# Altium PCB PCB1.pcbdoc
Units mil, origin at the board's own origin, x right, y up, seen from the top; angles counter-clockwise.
Board outline 3937.01 x 3937.01 mil, 2 copper layers (Top Layer, Bottom Layer); 25 components, 44 nets, 119 pads, 18 vias.
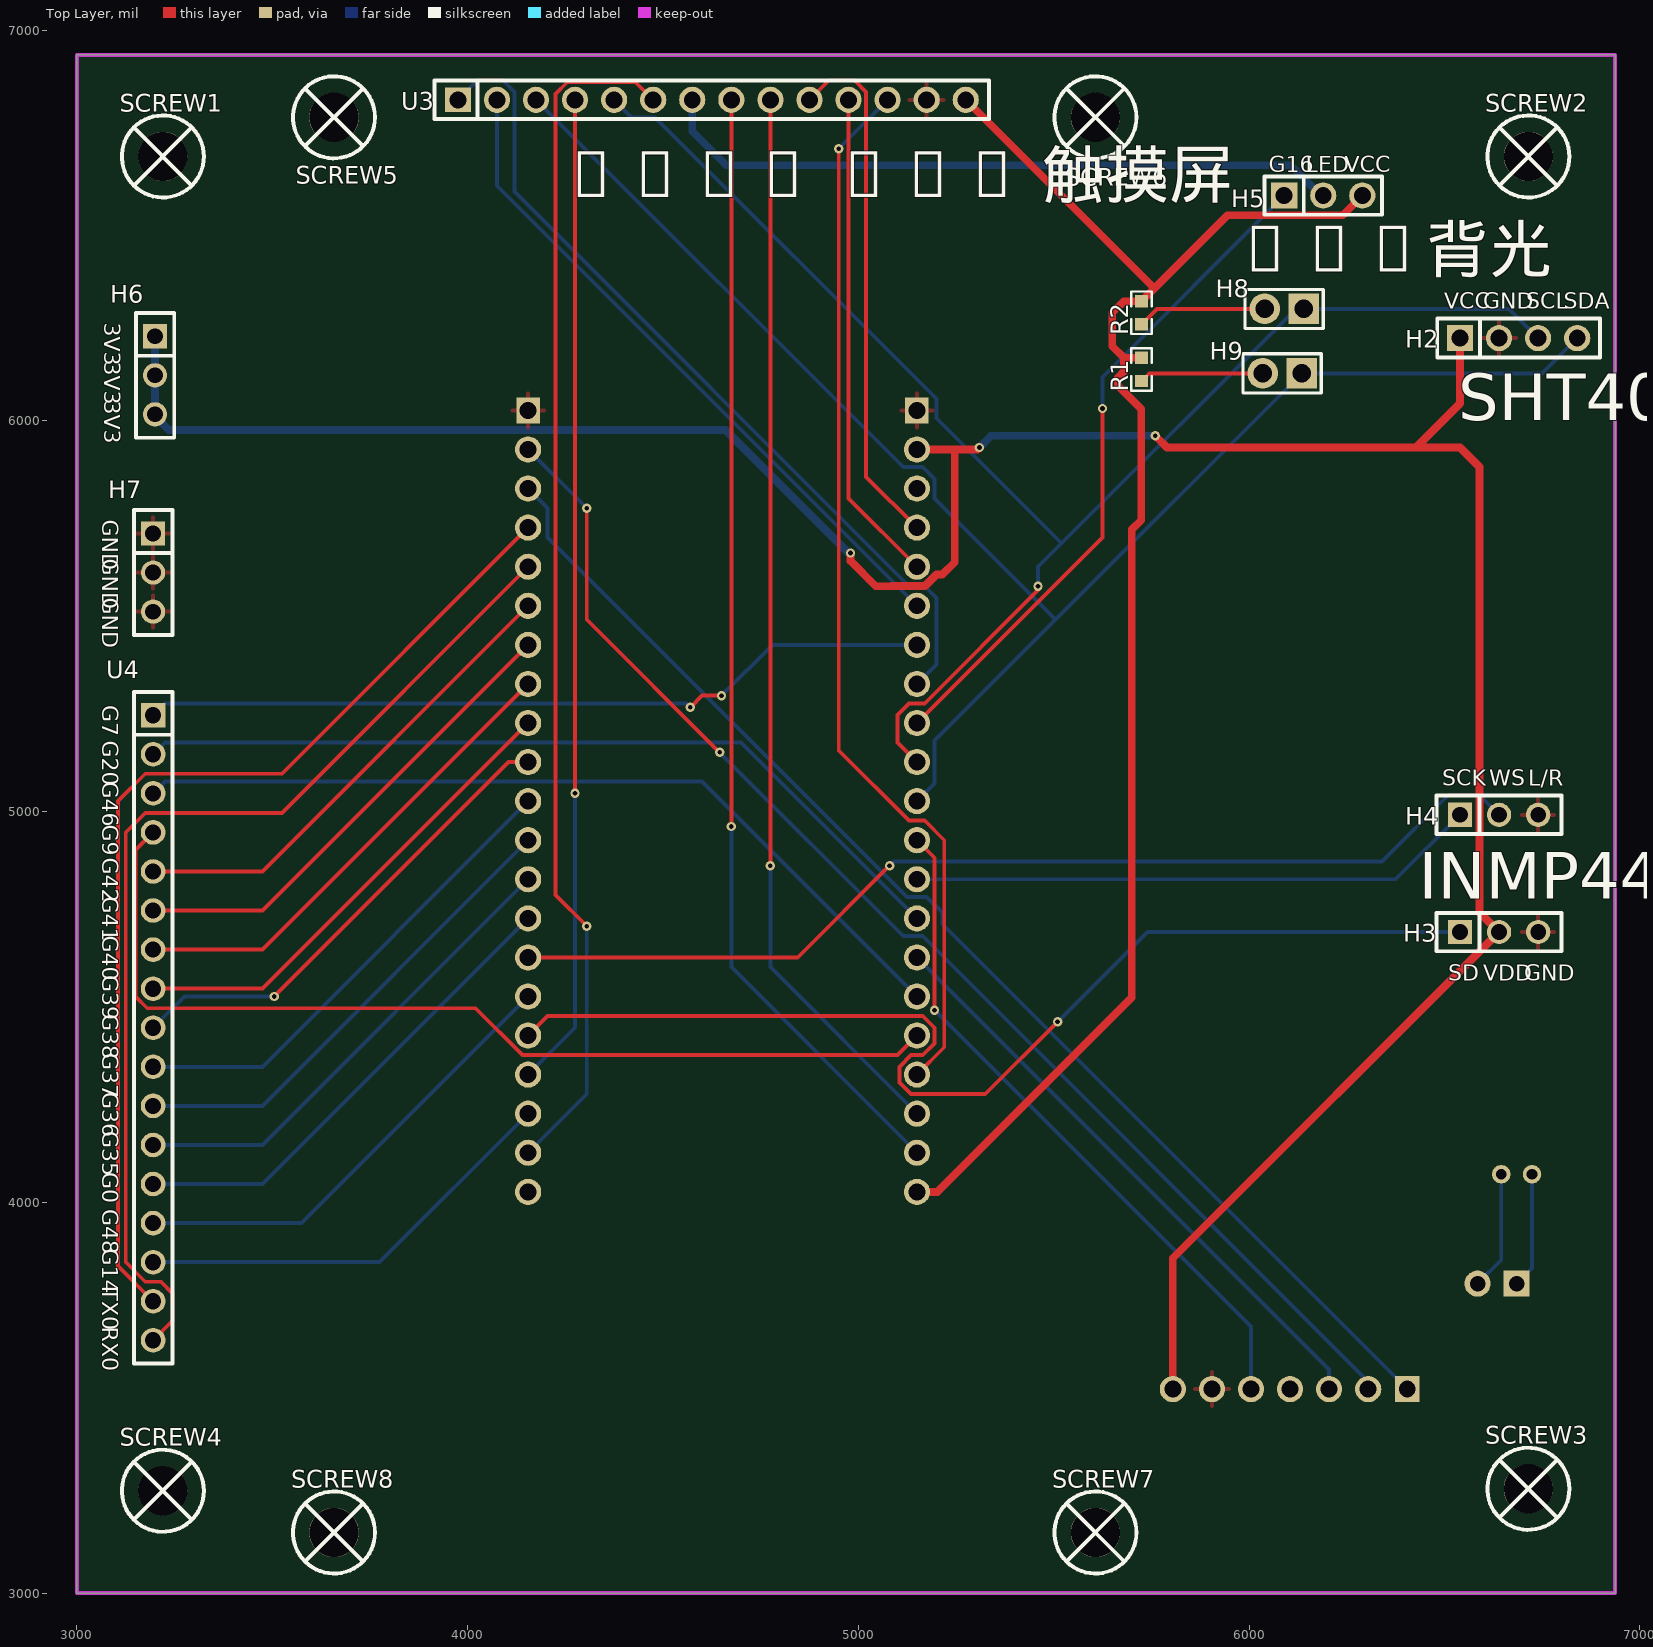
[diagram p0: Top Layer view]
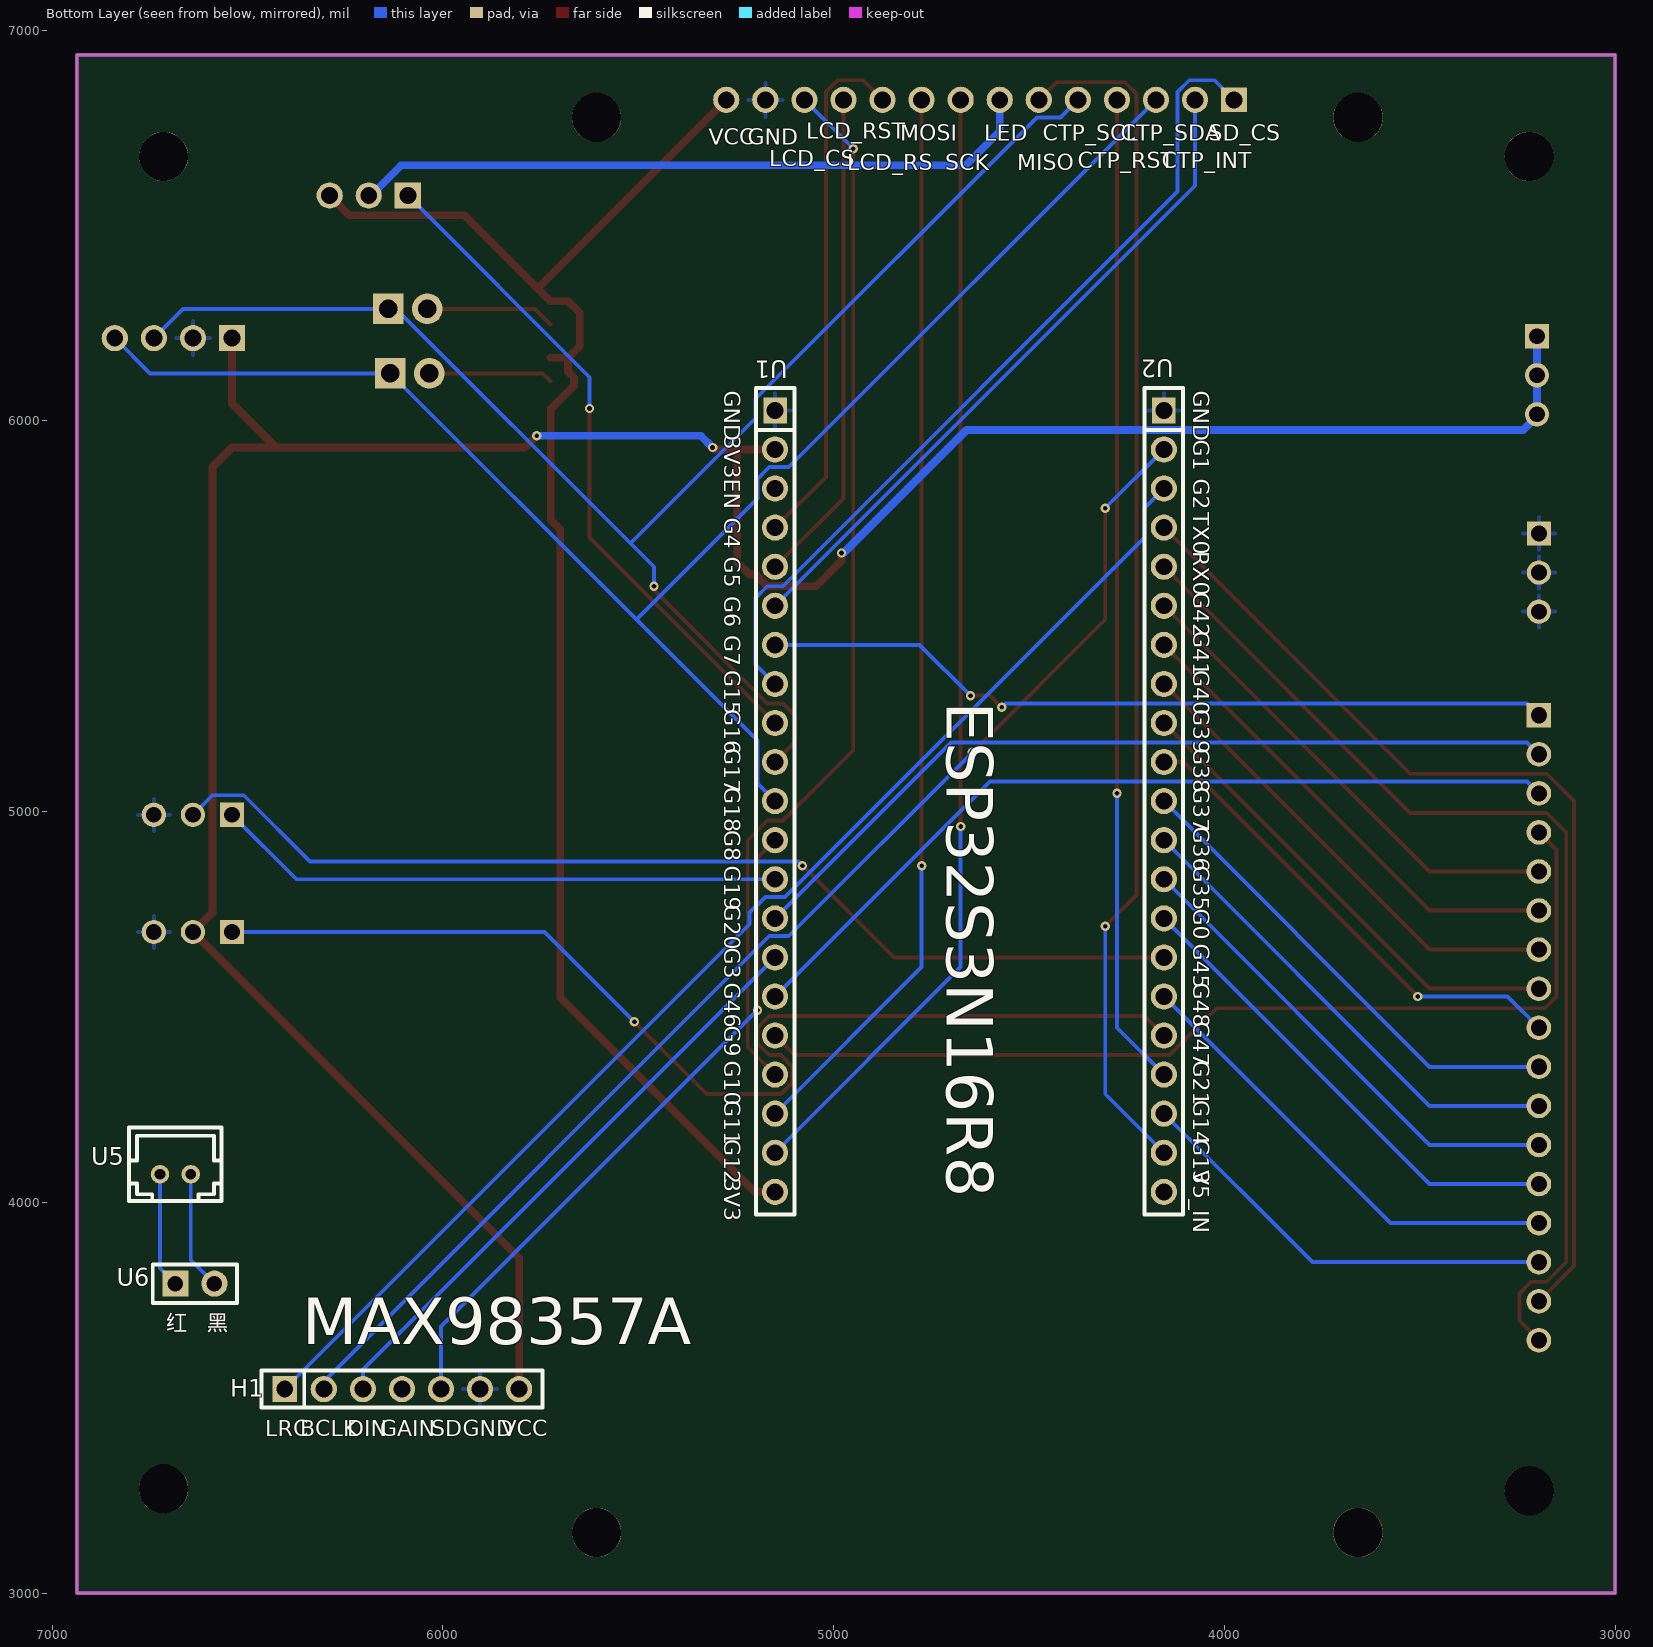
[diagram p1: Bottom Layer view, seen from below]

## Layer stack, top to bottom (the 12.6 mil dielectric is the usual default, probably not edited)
Top Layer: signal copper (thickness not stored)
Dielectric: dielectric 12.6, FR-4, Dk 4.8
Bottom Layer: signal copper (thickness not stored)

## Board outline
3000,6937.01 6937.01,6937.01 6937.01,3000 3000,3000

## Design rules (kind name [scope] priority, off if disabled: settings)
BoardOutlineClearance copperThickness1oz [All] p0: genericclearance=10 ignorepadtopadclearanceinfootprint=FALSE except(0: Arc-SplitContinuation Track-SplitContinuation SMDPad-SplitContinuation THPad-SplitContinuation Via-SplitContinuation Fill-SplitContinuation Poly-SplitContinuation Region-SplitContinuation Text-SplitContinuation; 6: Track-CutoutEdge SMDPad-CutoutEdge THPad-CutoutEdge Via-CutoutEdge Region-CutoutEdge; 11.8: Track-OutlineEdge SMDPad-OutlineEdge THPad-OutlineEdge Via-OutlineEdge Fill-OutlineEdge Region-OutlineEdge Poly-OutlineEdge Text-OutlineEdge Fill-CutoutEdge)
BoardOutlineClearance copperThickness2oz [All] p0: genericclearance=10 ignorepadtopadclearanceinfootprint=FALSE except(0: Arc-SplitContinuation Track-SplitContinuation SMDPad-SplitContinuation THPad-SplitContinuation Via-SplitContinuation Fill-SplitContinuation Poly-SplitContinuation Region-SplitContinuation Text-SplitContinuation; 6: Track-CutoutEdge SMDPad-CutoutEdge THPad-CutoutEdge Via-CutoutEdge Region-CutoutEdge; 11.8: Track-OutlineEdge SMDPad-OutlineEdge THPad-OutlineEdge Via-OutlineEdge Fill-OutlineEdge Region-OutlineEdge Poly-OutlineEdge Text-OutlineEdge Fill-CutoutEdge)
Clearance copperThickness1oz [(InNet('GND') OR InNet('DIN') OR InNet('BCLK') OR InNet('LRC') OR InNet('WS') OR InNet('SCK') OR InNet('VCC3.3V') OR InNet('GPIO7') OR InNet('GPIO16') OR InNet('GPIO20') OR InNet('GPIO46') OR InNet('GPIO9') OR InNet('TXD0') OR InNet('RXD0') OR InNet('GPIO42') OR InNet('GPIO41') OR InNet('GPIO40') OR InNet('GPIO39') OR InNet('GPIO38') OR InNet('GPIO37') OR InNet('GPIO36') OR InNet('GPIO35') OR InNet('GPIO0') OR InNet('GPIO48') OR InNet('GPIO14') OR InNet('LCD_CS') OR InNet('LCD_RST') OR InNet('LCD_RS') OR InNet('MOSI') OR InNet('LED') OR InNet('MISO') OR InNet('CTP_SCL') OR InNet('CTP_RST') OR InNet('CTP_SDA') OR InNet('CTP_INT') OR InNet('SD_CS') OR InNet('MAX_SD') OR InNet('IP_SD') OR InNet('IP_SCK') OR InNet('3V3') OR InNet('CTP_SCL1') OR InNet('CTP_SDA1') OR InNet('-') OR InNet('+'))] p1: gap=7 ignorepadtopadclearanceinfootprint=FALSE except(4: Track-Track; 6: Track-SMDPad SMDPad-SMDPad Track-THPad SMDPad-THPad THPad-THPad Track-Via SMDPad-Via THPad-Via Via-Via SMDPad-Fill THPad-Fill Via-Fill Fill-Fill Track-Region SMDPad-Region THPad-Region Via-Region Region-Region Track-Poly SMDPad-Poly THPad-Poly Via-Poly Fill-Poly Region-Poly Poly-Poly Track-Text SMDPad-Text THPad-Text Via-Text Fill-Text Region-Text Poly-Text Text-Text; 6.9: Track-Hole SMDPad-Hole THPad-Hole Via-Hole Fill-Hole Region-Hole Poly-Hole Text-Hole Sheet-Hole; 11.8: Track-Fill Fill-Region Track-Sheet SMDPad-Sheet THPad-Sheet Via-Sheet Fill-Sheet Region-Sheet Poly-Sheet Text-Sheet)
Clearance copperThickness2oz [All] p1: gap=7 ignorepadtopadclearanceinfootprint=FALSE except(6: Track-SMDPad SMDPad-SMDPad Track-THPad SMDPad-THPad THPad-THPad Track-Via SMDPad-Via THPad-Via Via-Via SMDPad-Fill THPad-Fill Via-Fill Fill-Fill Track-Region SMDPad-Region THPad-Region Via-Region Region-Region Track-Poly SMDPad-Poly THPad-Poly Via-Poly Fill-Poly Region-Poly Poly-Poly Track-Text SMDPad-Text THPad-Text Via-Text Fill-Text Region-Text Poly-Text Text-Text; 6.9: Track-Hole SMDPad-Hole THPad-Hole Via-Hole Fill-Hole Region-Hole Poly-Hole Text-Hole Sheet-Hole; 8: Track-Track; 11.8: Track-Fill Fill-Region Track-Sheet SMDPad-Sheet THPad-Sheet Via-Sheet Fill-Sheet Region-Sheet Poly-Sheet Text-Sheet)
DiffPairsRouting differentialPair [All] p1: maxuncoupledlength=10 minlimit=6 maxlimit=6 mostfreqgap=6 toplayer_minwidth=5 toplayer_prefwidth=10 toplayer_maxwidth=100 bottomlayer_minwidth=5 bottomlayer_prefwidth=10 bottomlayer_maxwidth=100
PasteMaskExpansion pasteMaskExpansion [All] p1: expansion=0
PlaneConnect innerPlane [All] p1: planeconnectstyle=Relief reliefexpansion=20 reliefentries=4 reliefconductorwidth=10 reliefairgap=10
PolygonConnect copperRegion [All] p1: connectstyle=Relief reliefentries=4 reliefconductorwidth=10 polygonreliefangle="90 Angle" airgapwidth=10
RoutingVias viaSize [All] p1: viastyle="Through Hole" holewidth=12.0078 minholewidth=11.811 maxholewidth=248.0314 width=24.0158 minwidth=19.685 maxwidth=393.7008
SolderMaskExpansion solderMaskExpansion [All] p1: useseparateexpansions=TRUE expansion=2 expansionbottom=2
Width copperThickness1oz [All] p1: maxlimit=100 minlimit=5 preferedwidth=10
Width copperThickness2oz [All] p1: maxlimit=100 minlimit=8 preferedwidth=10

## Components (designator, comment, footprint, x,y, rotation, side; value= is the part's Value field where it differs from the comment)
H1 "PM254V-11-07-H85" HDR-TH_7P-P2.54-V-F 6105,3522.01 r180 bottom
H2 "2.54-1*4P母" HDR-TH_4P-P2.54-V-F 6690,6212.01 r0 top
H3 "X6511FV-03-C85D32" HDR-TH_3P-P2.54-V-F 6640,4692.01 r0 top
H4 "X6511FV-03-C85D32" HDR-TH_3P-P2.54-V-F 6640,4992.01 r0 top
H5 "PZ254V-11-03P" HDR-TH_3P-P2.54-V-M 6190,6577.01 r0 top
H6 "X6511FV-03-C85D32" HDR-TH_3P-P2.54-V-F 3200,6117.01 r270 top
H7 "X6511FV-03-C85D32" HDR-TH_3P-P2.54-V-F 3195,5612.01 r270 top
H8 "PZ254V-11-02P" HDR-TH_2P-P2.54-V-M 6090,6287.01 r180 top
H9 "PZ254V-11-02P" HDR-TH_2P-P2.54-V-M 6085,6122.01 r180 top
R1 "RCA034K7JLF" R0603 5725,6132.01 r90 top
R2 "RCA034K7JLF" R0603 5725,6277.01 r90 top
SCREW1 "M3螺丝" M3螺丝 3220,6677.01 r0 top
SCREW2 "M3螺丝" M3螺丝 6715,6677.01 r0 top
SCREW3 "M3螺丝" M3螺丝 6715,3267.01 r0 top
SCREW4 "M3螺丝" M3螺丝 3220,3262.01 r0 top
SCREW5 "M3螺丝" M3螺丝 3658.07,6777.17 r0 top
SCREW6 "M3螺丝" M3螺丝 5606.89,6777.17 r0 top
SCREW7 "M3螺丝" M3螺丝 5606.89,3155.12 r0 top
SCREW8 "M3螺丝" M3螺丝 3658.07,3155.12 r0 top
U1 "HC-PM254-8.5H-1x21PZ" HDR-TH_21P-P2.54-V-F_1 5150,5027.01 r270 bottom
U2 "HC-PM254-8.5H-1x21PZ" HDR-TH_21P-P2.54-V-F_1 4155,5027.01 r270 bottom
U3 "PM254-1-14-Z-8.5" HDR-TH_14P-P2.54-V-F-1 4625,6822.01 r0 top
U4 "PM254-1-17-Z-8.5" HDR-TH_17P-P2.54-V-F 3195,4447.01 r270 top
U5 "HX 2.0mm-2P ZZ-MS" CONN-TH_2P-P2.00_HX-2.0MM-2P-ZZ 6685,4072.01 r180 bottom
U6 "ZX-PM2.54-1-2PY" HDR-TH_2P-P2.54-V-F 6635,3792.01 r180 bottom

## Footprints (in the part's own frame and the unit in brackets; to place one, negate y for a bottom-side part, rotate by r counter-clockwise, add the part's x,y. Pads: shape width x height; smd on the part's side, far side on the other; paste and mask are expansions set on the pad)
CONN-TH_2P-P2.00_HX-2.0MM-2P-ZZ [mm]
  round 1.2 hole 0.7: 1(-1,0) 2(1,0)
  silkscreen extent -3,-1.75 3,3.05
HDR-TH_2P-P2.54-V-F [mm]
  rect 1.7x1.7 hole 1: 1(-1.27,0)
  round 1.7 hole 1: 2(1.27,0)
  silkscreen extent -2.74,-1.25 2.74,1.25
HDR-TH_2P-P2.54-V-M [mm]
  rect 2x2 hole 1.2: 1(-1.27,0)
  round 2 hole 1.2: 2(1.27,0)
  silkscreen extent -2.54,-1.27 2.54,1.27
HDR-TH_3P-P2.54-V-F [mil]
  rect 62x62 hole 40.16: 1(-100,0)
  round 62 hole 40.16: 2(0,0) 3(100,0)
  silkscreen extent -160,-49 160,49
HDR-TH_3P-P2.54-V-M [mm]
  rect 1.7x1.7 hole 1.1: 1(-2.54,0)
  round 1.7 hole 1.1: 2(0,0) 3(2.54,0)
  silkscreen extent -3.81,-1.25 3.81,1.25
HDR-TH_4P-P2.54-V-F [mm]
  rect 1.7x1.7 hole 1.1: 1(-3.81,0)
  round 1.7 hole 1.1: 2(-1.27,0) 3(1.27,0) 4(3.81,0)
  silkscreen extent -5.29,-1.27 5.29,1.27
HDR-TH_7P-P2.54-V-F [mm]
  rect 1.575x1.7 hole 1.1: 1(-7.62,0)
  round 1.7 hole 1.1: 2(-5.08,0) 3(-2.54,0) 4(0,0) 5(2.54,0) 6(5.08,0) 7(7.62,0)
  silkscreen extent -9.13,-1.2 9.13,1.2
HDR-TH_14P-P2.54-V-F-1 [mm]
  rect 1.7x1.575 hole 1.1: 1(-16.51,0)
  round 1.7 hole 1.1: 2(-13.97,0) 3(-11.43,0) 4(-8.89,0) 5(-6.35,0) 6(-3.81,0) 7(-1.27,0) 8(1.27,0) 9(3.81,0) 10(6.35,0) 11(8.89,0) 12(11.43,0) 13(13.97,0) 14(16.51,0)
  silkscreen extent -18.03,-1.25 18.03,1.25
HDR-TH_17P-P2.54-V-F [mm]
  rect 1.6x1.6 hole 1.05: 1(-20.32,0)
  round 1.6 hole 1.05: 2(-17.78,0) 3(-15.24,0) 4(-12.7,0) 5(-10.16,0) 6(-7.62,0) 7(-5.08,0) 8(-2.54,0) 9(0,0) 10(2.54,0) 11(5.08,0) 12(7.62,0) 13(10.16,0) 14(12.7,0) 15(15.24,0) 16(17.78,0) 17(20.32,0)
  silkscreen extent -21.84,-1.25 21.84,1.25
HDR-TH_21P-P2.54-V-F_1 [mm]
  rect 1.7x1.524 hole 1.1: 1(-25.4,0)
  round 1.7 hole 1.1: 2(-22.86,0) 3(-20.32,0) 4(-17.78,0) 5(-15.24,0) 6(-12.7,0) 7(-10.16,0) 8(-7.62,0) 9(-5.08,0) 10(-2.54,0) 11(0,0) 12(2.54,0) 13(5.08,0) 14(7.62,0) 15(10.16,0) 16(12.7,0) 17(15.24,0) 18(17.78,0) 19(20.32,0) 20(22.86,0) 21(25.4,0)
  silkscreen extent -26.87,-1.25 26.87,1.25
M3螺丝 [mil]
  round 126 hole 126: 1(0,0)
  silkscreen extent -105,-105 105,105
R0603 [mil]
  rect 31.75x34.02 smd: 1(-29.66,0) 2(29.66,0)
  silkscreen extent -55,-26 55,26

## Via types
v1: diameter 24.02, hole 12.01, Top Layer to Bottom Layer, 18 vias

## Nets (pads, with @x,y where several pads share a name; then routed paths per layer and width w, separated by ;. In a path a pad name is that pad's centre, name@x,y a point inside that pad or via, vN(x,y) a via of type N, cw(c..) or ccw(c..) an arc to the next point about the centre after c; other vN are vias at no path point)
3V3: H5.3 R1.2 R2.2 U1.21 U3.14 | length 4054.8
  Top Layer w20: U1.21 5202.52,4027.01 5700,4524.49 5700,5722.19 5724.02,5746.2 5724.02,6030.51 5665,6089.52 5665,6111.67 5680,6126.67 5680,6161.67 ; U3.14 5755,6342.01 5755,6336.67 ; R1.2 5680,6161.67 ; H5.3 6239.66,6526.67 5945,6526.67 5755,6336.67 ; 5680,6161.67 5650,6191.67 5650,6276.67 5680,6306.67 R2.2 5755,6336.67
+: U5.1 U6.1 | length 296.3
  Bottom Layer w10: U6.1 6724.37,3831.38 U5.1
-: U5.2 U6.2 | length 305.1
  Bottom Layer w10: U6.2 6645.63,3852.64 U5.2
BCLK: H1.2 U2.2 | length 3324.8
  Top Layer w10: v1(4305,5777.01) 4305,5492.01 v1(4645,5152.01)
  Bottom Layer w10: U2.2 v1(4305,5777.01) ; v1(4645,5152.01) 5115,4682.01 5165,4682.01 6305,3542.01 H1.2
CTP_INT: U1.6 U3.2 | length 1740.3
  Bottom Layer w10: U3.2 4075,6602.01 U1.6
CTP_RST: U2.18 U3.4 | length 2544.7
  Top Layer w10: v1(4275,5047.01) U3.4
  Bottom Layer w10: U2.18 4275,4447.01 v1(4275,5047.01)
CTP_SCL: H2.3 H8.1 U1.10 U3.5 | length 3922.1
  Top Layer w10: U1.10 5100,5177.01 5100,5247.01 5130,5277.01 5170,5277.01 5460,5567.01 v1(5460,5577.01)
  Bottom Layer w10: U3.5 4420,6777.01 4480,6777.01 5200,6057.01 5200,6007.01 5520,5687.01 ; v1(5460,5577.01) 5460,5627.01 5520,5687.01 ; H2.3 6665,6287.01 H8.1 6120,6287.01 5520,5687.01
CTP_SCL1: H8.2 R2.1 | length 331.4
  Top Layer w10: R2.1 5764.66,6287.01 H8.2
CTP_SDA: H2.4 H9.1 U1.11 U3.3 | length 4155.5
  Bottom Layer w10: U3.3 5115,5882.01 5165,5882.01 5195,5852.01 5195,5802.01 5505,5492.01 ; U1.11 5195,5072.01 5195,5182.01 5505,5492.01 ; H2.4 6750,6122.01 H9.1 5505,5492.01
CTP_SDA1: H9.2 R1.1 | length 318.1
  Top Layer w10: R1.1 5744.66,6122.01 H9.2
DIN: H1.3 U1.15 | length 1542
  Bottom Layer w10: U1.15 6205,3572.01 H1.3
GND: H1.6 H2.2 H3.3 H4.3 H7.1 H7.2 H7.3 U1.1 U2.1 U3.13
GPIO0: U2.14 U4.13 | length 1241.7
  Bottom Layer w10: U4.13 3475,4047.01 U2.14
GPIO7: U1.7 U4.1 | length 2037.8
  Top Layer w10: v1(4570,5267.01) 4600,5297.01 v1(4650,5297.01)
  Bottom Layer w10: U4.1 3225,5277.01 4560,5277.01 v1(4570,5267.01) ; v1(4650,5297.01) 4780,5427.01 U1.7
GPIO9: U1.17 U4.4 | length 2521.5
  Top Layer w10: U4.4 3150,4902.01 3150,4527.01 3180,4497.01 4020,4497.01 4140,4377.01 5100,4377.01 U1.17
GPIO14: U2.19 U4.15 | length 1117.4
  Bottom Layer w10: U4.15 3775,3847.01 U2.19
GPIO16: H5.1 U1.9 | length 1739.4
  Top Layer w10: U1.9 5625,5702.01 v1(5625,6032.01)
  Bottom Layer w10: v1(5625,6032.01) 5625,6112.01 H5.1
GPIO20: U1.14 U4.2 | length 2153.8
  Bottom Layer w10: U4.2 3225,5177.01 4700,5177.01 U1.14
GPIO35: U2.13 U4.12 | length 1241.7
  Bottom Layer w10: U4.12 3475,4147.01 U2.13
GPIO36: U2.12 U4.11 | length 1241.7
  Bottom Layer w10: U4.11 3475,4247.01 U2.12
GPIO37: U2.11 U4.10 | length 1241.7
  Bottom Layer w10: U4.10 3475,4347.01 U2.11
GPIO38: U2.10 U4.9 | length 1241.7
  Top Layer w10: v1(3505,4527.01) 4105,5127.01 U2.10
  Bottom Layer w10: U4.9 3275,4527.01 v1(3505,4527.01)
GPIO39: U2.9 U4.8 | length 1241.7
  Top Layer w10: U4.8 3475,4547.01 U2.9
GPIO40: U2.8 U4.7 | length 1241.7
  Top Layer w10: U4.7 3475,4647.01 U2.8
GPIO41: U2.7 U4.6 | length 1241.7
  Top Layer w10: U4.6 3475,4747.01 U2.7
GPIO42: U2.6 U4.5 | length 1241.7
  Top Layer w10: U4.5 3475,4847.01 U2.6
GPIO46: U1.16 U4.3 | length 2195.2
  Bottom Layer w10: U4.3 3225,5077.01 4600,5077.01 U1.16
GPIO48: U2.16 U4.14 | length 1200.2
  Bottom Layer w10: U4.14 3575,3947.01 U2.16
IP_SCK: H4.1 U1.13 | length 1458.3
  Bottom Layer w10: U1.13 6375,4827.01 H4.1
IP_SD: H3.1 U2.17 | length 2887.3
  Top Layer w10: U2.17 4205,4477.01 5165,4477.01 5195,4447.01 5195,4407.01 5165,4377.01 5135,4377.01 5105,4347.01 5105,4307.01 5135,4277.01 5325,4277.01 v1(5510,4462.01)
  Bottom Layer w10: v1(5510,4462.01) 5740,4692.01 H3.1
LCD_CS: U1.18 U3.12 | length 2711
  Top Layer w10: v1(4950,6697.01) 4950,5157.01 5130,4977.01 5170,4977.01 5220,4927.01 5220,4397.01 U1.18
  Bottom Layer w10: v1(4950,6697.01) U3.12
LCD_RS: U1.4 U3.10 | length 1347
  Top Layer w10: U3.10 4925,6872.01 4990,6872.01 5020,6842.01 5020,5857.01 U1.4
LCD_RST: U1.5 U3.11 | length 1267.5
  Top Layer w10: U3.11 4975,5802.01 U1.5
LED: H5.2 U3.7 | length 1763.6
  Bottom Layer w20: U3.7 4575,6741.52 4662.09,6654.43 6107.11,6654.43 6179.53,6582.01 6185,6582.01 H5.2
LRC: H1.1 U2.3 | length 3266.3
  Bottom Layer w10: U2.3 4205,5777.01 4205,5702.01 5125,4782.01 5175,4782.01 5215,4742.01 5215,4712.01 H1.1
MAX_SD: H1.5 U1.12 | length 1759.2
  Top Layer w10: U1.12 5195,4882.01 v1(5195,4492.01)
  Bottom Layer w10: v1(5195,4492.01) 6005,3682.01 H1.5
MISO: U2.20 U3.6 | length 3086.3
  Top Layer w10: v1(4305,4707.01) 4225,4787.01 4225,6837.01 4255,6867.01 4430,6867.01 U3.6
  Bottom Layer w10: U2.20 4305,4277.01 v1(4305,4707.01)
MOSI: U1.19 U3.9 | length 2750.3
  Top Layer w10: v1(4775,4862.01) U3.9
  Bottom Layer w10: v1(4775,4862.01) 4775,4602.01 U1.19
RXD0: U2.5 U4.17 | length 2705.5
  Top Layer w10: U4.17 3245,3697.01 3245,3767.01 3215,3797.01 3175,3797.01 3125,3847.01 3125,4947.01 3175,4997.01 3525,4997.01 U2.5
SCK: U1.20 U3.8 | length 2891.8
  Top Layer w10: v1(4675,4962.01) U3.8
  Bottom Layer w10: v1(4675,4962.01) 4675,4602.01 U1.20
SD_CS: U1.8 U3.1 | length 2184.6
  Bottom Layer w10: U3.1 4025,6872.01 4090,6872.01 4120,6842.01 4120,6587.01 5130,5577.01 5170,5577.01 5200,5547.01 5200,5377.01 U1.8
TXD0: U2.4 U4.16 | length 2657.2
  Top Layer w10: U4.16 3105,3837.01 3105,5027.01 3175,5097.01 3525,5097.01 U2.4
VCC3.3V: H1.7 H2.1 H3.2 H6.1 H6.2 H6.3 U1.2 | length 7298.4
  Top Layer w20: v1(4980,5662.01) 4980,5642.01 5045,5577.01 5085,5577.01 5085.55,5577.56 5170.48,5577.56 5199.93,5607.01 5215,5607.01 5246.85,5638.86 5246.85,5927.01 ; U1.2 5246.85,5927.01 ; v1(5310,5932.01) 5305,5927.01 5246.85,5927.01 ; v1(5760,5962.01) 5790,5932.01 6427.26,5932.01 ; H1.7 5805,3857.01 H3.2 6590,4742.01 6590,5882.01 6540,5932.01 6427.26,5932.01 ; H2.1 6540,6044.75 6427.26,5932.01
  Bottom Layer w20: H6.1 H6.2 H6.3 3200,6012.01 3235,5977.01 4660,5977.01 4975,5662.01 v1(4980,5662.01) ; v1(5310,5932.01) 5340,5962.01 v1(5760,5962.01)
WS: H4.2 U2.15 | length 2677.6
  Top Layer w10: U2.15 4845,4627.01 v1(5080,4862.01)
  Bottom Layer w10: v1(5080,4862.01) 5090,4872.01 6340,4872.01 6510,5042.01 6590,5042.01 H4.2
pads on no net: H1.4 SCREW1.1 SCREW2.1 SCREW3.1 SCREW4.1 SCREW5.1 SCREW6.1 SCREW7.1 SCREW8.1 U1.3 U2.21

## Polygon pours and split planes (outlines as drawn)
GND on Bottom Layer (solid, remove dead copper, pour order 2): 3000,6937.01 6937.01,6937.01 6937.01,3000 3000,3000
GND on Top Layer (solid, remove dead copper, pour order 0): 3000,6937.01 6937.01,6937.01 6937.01,3000 3000,3000

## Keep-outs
Board Outline Layer:
  the board outline again, w10

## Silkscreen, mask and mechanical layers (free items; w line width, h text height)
Top Silkscreen Layer:
  text "G16" at 6050,6637.01 h41.26
  text "LED" at 6145,6637.01 h41.26
  text "VCC" at 6245,6637.01 h41.26
  text "3.5` LCD 触摸屏" at 4235,6572.01 h120
  text "LCD背光" at 5960,6382.01 h120
  text "VCC" at 6500,6287.01 h41.26
  text "GND" at 6600,6287.01 h41.26
  text "SCL" at 6710,6287.01 h41.26
  text "SDA" at 6805,6287.01 h41.26
  text "3V3" at 3070,6252.01 h41.26 r270
  text "3V3" at 3070,6152.01 h41.26 r270
  text "3V3" at 3070,6052.01 h41.26 r270
  text "SHT40" at 6535,6002.01 h120
  text "GND" at 3065,5747.01 h41.26 r270
  text "GND" at 3065,5647.01 h41.26 r270
  text "GND" at 3065,5547.01 h41.26 r270
  text "G7" at 3065,5272.01 h41.26 r270
  text "G20" at 3065,5182.01 h41.26 r270
  text "G46" at 3065,5077.01 h41.26 r270
  text "SCK" at 6495,5067.01 h41.26
  text "WS" at 6615,5067.01 h41.26
  text "L/R" at 6715,5067.01 h41.26
  text "G9" at 3065,4967.01 h41.26 r270
  text "G42" at 3065,4882.01 h41.26 r270
  text "G41" at 3065,4782.01 h41.26 r270
  text "INMP441" at 6435,4777.01 h120
  text "G40" at 3065,4682.01 h41.26 r270
  text "G39" at 3065,4582.01 h41.26 r270
  text "SD" at 6510,4567.01 h41.26
  text "VDD" at 6600,4567.01 h41.26
  text "GND" at 6705,4567.01 h41.26
  text "G38" at 3065,4482.01 h41.26 r270
  text "G37" at 3065,4382.01 h41.26 r270
  text "G36" at 3065,4282.01 h41.26 r270
  text "G35" at 3065,4182.01 h41.26 r270
  text "G0" at 3065,4077.01 h41.26 r270
  text "G48" at 3065,3982.01 h41.26 r270
  text "G14" at 3065,3882.01 h41.26 r270
  text "TX0" at 3065,3782.01 h41.26 r270
  text "RX0" at 3065,3682.01 h41.26 r270
Bottom Silkscreen Layer:
  text "LCD_RST" at 5070,6722.01 h41.26
  text "SD_CS" at 4040,6717.01 h41.26
  text "CTP_SDA" at 4265,6717.01 h41.26
  text "CTP_SCL" at 4465,6717.01 h41.26
  text "LED" at 4615,6717.01 h41.26
  text "MOSI" at 4830,6717.01 h41.26
  text "GND" at 5220,6707.01 h41.26
  text "VCC" at 5320,6707.01 h41.26
  text "LCD_CS" at 5165,6652.01 h41.26
  text "CTP_INT" at 4160,6647.01 h41.26
  text "CTP_RST" at 4375,6647.01 h41.26
  text "MISO" at 4530,6642.01 h41.26
  text "SCK" at 4715,6642.01 h41.26
  text "LCD_RS" at 4965,6642.01 h41.26
  text "GND" at 4080,6077.01 h41.26 r90
  text "GND" at 5280,6077.01 h41.26 r90
  text "3V3" at 5280,5962.01 h41.26 r90
  text "G1" at 4080,5952.01 h41.26 r90
  text "G2" at 4080,5852.01 h41.26 r90
  text "EN" at 5280,5852.01 h41.26 r90
  text "TX0" at 4080,5767.01 h41.26 r90
  text "G4" at 5280,5752.01 h41.26 r90
  text "RX0" at 4080,5667.01 h41.26 r90
  text "G5" at 5280,5652.01 h41.26 r90
  text "G42" at 4080,5562.01 h41.26 r90
  text "G6" at 5280,5552.01 h41.26 r90
  text "G41" at 4080,5462.01 h41.26 r90
  text "G7" at 5280,5452.01 h41.26 r90
  text "G40" at 4080,5362.01 h41.26 r90
  text "G15" at 5280,5362.01 h41.26 r90
  text "ESP32S3N16R8" at 4710,5282.01 h120 r90
  text "G39" at 4080,5262.01 h41.26 r90
  text "G16" at 5280,5262.01 h41.26 r90
  text "G38" at 4080,5162.01 h41.26 r90
  text "G17" at 5280,5162.01 h41.26 r90
  text "G37" at 4080,5062.01 h41.26 r90
  text "G18" at 5280,5062.01 h41.26 r90
  text "G36" at 4080,4962.01 h41.26 r90
  text "G8" at 5280,4952.01 h41.26 r90
  text "G35" at 4080,4862.01 h41.26 r90
  text "G19" at 5280,4862.01 h41.26 r90
  text "G20" at 5280,4762.01 h41.26 r90
  text "G0" at 4080,4752.01 h41.26 r90
  text "G45" at 4080,4662.01 h41.26 r90
  text "G3" at 5280,4652.01 h41.26 r90
  text "G48" at 4080,4562.01 h41.26 r90
  text "G46" at 5280,4562.01 h41.26 r90
  text "G47" at 4080,4462.01 h41.26 r90
  text "G9" at 5280,4452.01 h41.26 r90
  text "G21" at 4080,4362.01 h41.26 r90
  text "G10" at 5280,4362.01 h41.26 r90
  text "G14" at 4080,4262.01 h41.26 r90
  text "G11" at 5280,4262.01 h41.26 r90
  text "G13" at 4080,4162.01 h41.26 r90
  text "G12" at 5280,4162.01 h41.26 r90
  text "V5_IN" at 4080,4082.01 h41.26 r90
  text "3V3" at 5280,4062.01 h41.26 r90
  text "黑" at 6605,3672.01 h41.26
  text "红" at 6710,3672.01 h41.26
  text "MAX98357A" at 6360,3637.01 h120
  text "VCC" at 5850,3402.01 h41.26
  text "GND" at 5950,3402.01 h41.26
  text "SD" at 6030,3402.01 h41.26
  text "GAIN" at 6160,3402.01 h41.26
  text "DIN" at 6245,3402.01 h41.26
  text "BCLK" at 6365,3402.01 h41.26
  text "LRC" at 6455,3402.01 h41.26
